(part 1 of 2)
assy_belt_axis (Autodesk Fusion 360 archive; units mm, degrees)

design "assy_belt_axis" references "circuit_mount_stepper_simple", "extrusion_ribbon_cable_sidebar", "belt_idler", "lil_foot", "belt_clip_update", "belt_motor_mount", "carriage_front_generic", "limit_mount", "FRM-Extrusion-VSlot-2020-350"
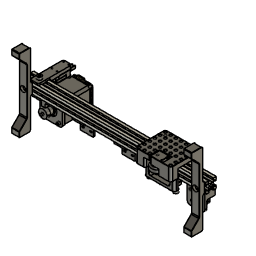
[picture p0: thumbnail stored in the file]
component_insert "Component Insert1" alignAngle 90 alignOffsetX 0 alignOffsetY 0 alignOffsetZ 0
joint "Assemble1" alignAngle -90 alignOffsetX 0 alignOffsetY 0 alignOffsetZ -6
component_insert "Component Insert2"
joint "Assemble2" alignAngle 0 alignOffsetX 0 alignOffsetY 0 alignOffsetZ -10
component_insert "Component Insert3"
joint "Assemble3" alignAngle 90 alignOffsetX 0 alignOffsetY 0 alignOffsetZ 0
component_insert "Component Insert4"
joint "Assemble4" alignAngle 0 alignOffsetX 0 alignOffsetY 30 alignOffsetZ 9
component_insert "Component Insert5"
joint "Assemble33" alignAngle 180 alignOffsetX 0 alignOffsetY -8 alignOffsetZ 11
component_insert "Component Insert6"
joint "Assemble6" alignAngle 270 alignOffsetX 0 alignOffsetY 21 alignOffsetZ 9
component_insert "Component Insert7"
joint "Assemble7" alignAngle 0 alignOffsetX 0 alignOffsetY 10 alignOffsetZ 6
component_insert "Component Insert8"
joint "Assemble8" alignAngle 0 alignOffsetX 0 alignOffsetY -10 alignOffsetZ 6
component_insert "Component Insert9"
joint "Assemble9" alignAngle 90 alignOffsetX 0 alignOffsetY 0 alignOffsetZ 0
component_insert "Component Insert32"
joint "Assemble32" alignAngle 270 alignOffsetX -70 alignOffsetY 0 alignOffsetZ 9
component_insert "Component Insert33"
joint "Assemble34" alignAngle -90 alignOffsetX 10 alignOffsetY 0 alignOffsetZ 9
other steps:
joint_origin "JointOrigin1"
joint_origin "JointOrigin2"
step "Assemble21" alignAngle -90 alignOffsetX 0 alignOffsetY 0 alignOffsetZ 0
step "Assemble22" alignAngle -90 alignOffsetX 0 alignOffsetY 0 alignOffsetZ 0
step "Assemble23" alignAngle 180 alignOffsetX 0 alignOffsetY 0 alignOffsetZ 0
step "Assemble24" alignAngle 90 alignOffsetX 0 alignOffsetY 0 alignOffsetZ 0
step "Assemble25" alignAngle 90 alignOffsetX 0 alignOffsetY 0 alignOffsetZ 0
step "Assemble26" alignAngle 90 alignOffsetX 0 alignOffsetY 0 alignOffsetZ 0
step "Assemble27" alignAngle 90 alignOffsetX 0 alignOffsetY 0 alignOffsetZ 0
step "Assemble28" alignAngle 0 alignOffsetX 0 alignOffsetY 0 alignOffsetZ 0
step "Assemble29" alignAngle 0 alignOffsetX 0 alignOffsetY 0 alignOffsetZ 0
step "Assemble30" alignAngle 0 alignOffsetX 0 alignOffsetY 0 alignOffsetZ 0
step "Assemble31" alignAngle 0 alignOffsetX 0 alignOffsetY 0 alignOffsetZ 0

design "lil_foot"
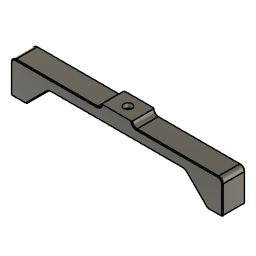
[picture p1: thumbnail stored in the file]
sketch "Sketch1" plane through (0, 0, 0) normal (0, 1, 0) x axis (1, 0, 0)
  line L1 (0, 0) -> (-10, 0)
  line L2 (-10, 3) -> (-10, 0)
  line L3 (-70, 3) -> (-10, 3)
  line L4 (-70, 25) -> (-70, 3)
  line L5 (-60, 25) -> (-70, 25)
  line L6 (-45, 10) -> (-60, 25)
  line L7 (0, 10) -> (-45, 10)
  line L8 (0, 0) -> (0, 10)
  line L9 (0, 0) -> (10, 0)
  line L10 (10, 3) -> (10, 0)
  line L11 (70, 3) -> (10, 3)
  line L12 (70, 25) -> (70, 3)
  line L13 (60, 25) -> (70, 25)
  line L14 (45, 10) -> (60, 25)
  line L15 (0, 10) -> (45, 10)
  point P1 (0, 0)
  point P9 (0, 0)
  point P10 (0, 0)
  point P2 (-10, 0)
  point P11 (10, 0)
  point P3 (-10, 3)
  point P13 (10, 3)
  point P4 (-70, 3)
  point P14 (70, 3)
  point P5 (-70, 25)
  point P15 (70, 25)
  point P6 (-60, 25)
  point P16 (60, 25)
  point P7 (-45, 10)
  point P17 (45, 10)
  point P8 (0, 10)
  point P18 (0, 10)
  point P12 (0, 0)
  horizontal L1
  perpendicular L1 L2
  perpendicular L2 L3
  perpendicular L3 L4
  perpendicular L4 L5
  perpendicular L4 L7
  perpendicular L7 L8
  coincident P1 P9
  coincident L8 P10
  coincident P1 P10
  symmetric P2 L8 P11
  symmetric P3 L8 P13
  symmetric P4 L8 P14
  symmetric P5 L8 P15
  symmetric P6 L8 P16
  symmetric P7 L8 P17
  symmetric P8 L8 P18
  symmetric L8 P10 P12
  dimension "d2" distance P2 P10 = 10
  dimension "d4" angle L6 L7 = 45
  dimension "d5" distance P5 P6 = 10
  dimension "d6" distance P6 P7 = 15
  dimension "d8" distance P5 P8 = 70 (= "( 140 / 2 ) * 1 mm")
  dimension "d9" distance P2 P3 = 3
  dimension "d11" distance P2 P5 = 25
  dimension "d12" distance P1 P8 = 10
extrude "Extrude1" new body sketch "Sketch1" profile of L1 L2 L3 L4 L5 L6 L7 L9 L10 L11 L12 L13 L14 L15 along normal blind 15
sketch "Sketch2" plane through (0, 0, 0) normal (0, 0, 1) x axis (-1, 0, 0)
  line L1 (-10, 0) -> (10, 0)
  line L2 (-10, -15) -> (-10, 0)
  line L3 (10, -15) -> (-10, -15)
  line L4 (10, 0) -> (10, -15)
  line L5 (0, -15) -> (0, 0)
  circle C1 centre (0, -7.5) radius 2.75
  circle C2 centre (0, -7.5) radius 5.25
  point P1 (0, 0)
  point P6 (0, 0)
  point P7 (0, -15)
  point P8 (0, -7.5)
  coincident P1 P6
  midpoint L3 P7
  midpoint L5 P8
  concentric C1 C2
  dimension "d15" diameter C2 = 10.5
  dimension "d16" diameter C1 = 5.5
extrude "Extrude2" cut sketch "Sketch2" profile of C1 to an object
extrude "Extrude3" cut sketch "Sketch2" profile of L2 L4 C1 C2 no distance stored from offset -5.5
chamfer "Chamfer1" distance 2.5
fillet "Fillet1" radius 3
fillet "Fillet2" radius 1
chamfer "Chamfer2" distance 0.5
named bodies: "lil_foot"

design "FRM-Extrusion-VSlot-2020-350"
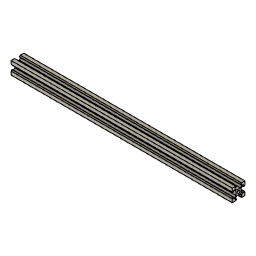
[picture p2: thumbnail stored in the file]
parameter "d90" = 4
parameter "d92" = 0.75 (= "( 1.5 / 2 ) * 1 mm")
sketch "Sketch4" plane through (0, 0, 0) normal (1, 0, 0) x axis (0, 1, 0)
  line L1 (20, 0) -> (0, 0)
  line L2 (20, 20) -> (20, 0)
  line L3 (0, 20) -> (20, 20)
  line L4 (0, 0) -> (0, 20)
  line L5 (10, 0) -> (10, 20)
  line L6 (0, 10) -> (20, 10)
  line L7 (15.5, 18.2) -> (13.125, 18.2)
  line L8 (12.9393, 14) -> (15.5, 16.5607)
  line L9 (10, 14) -> (12.9393, 14)
  line L10 (20, 20) -> (10, 10)
  line L11 (13.125, 18.545) -> (13.125, 18.2)
  line L12 (14.58, 20) -> (13.125, 18.545)
  line L13 (15.5, 16.5607) -> (15.5, 18.2)
  line L14 (20, 14.58) -> (18.545, 13.125)
  line L15 (18.545, 13.125) -> (18.2, 13.125)
  line L16 (16.5607, 15.5) -> (18.2, 15.5)
  line L17 (14, 12.9393) -> (16.5607, 15.5)
  line L18 (14, 10) -> (14, 12.9393)
  line L19 (18.2, 15.5) -> (18.2, 13.125)
  line L20 (5.42, 20) -> (6.875, 18.545)
  line L21 (6.875, 18.545) -> (6.875, 18.2)
  line L22 (4.5, 18.2) -> (6.875, 18.2)
  line L23 (4.5, 16.5607) -> (4.5, 18.2)
  line L24 (10, 14) -> (7.0607, 14)
  line L25 (7.0607, 14) -> (4.5, 16.5607)
  line L26 (0, 14.58) -> (1.455, 13.125)
  line L27 (1.455, 13.125) -> (1.8, 13.125)
  line L28 (1.8, 15.5) -> (1.8, 13.125)
  line L29 (3.4393, 15.5) -> (1.8, 15.5)
  line L30 (6, 10) -> (6, 12.9393)
  line L31 (6, 12.9393) -> (3.4393, 15.5)
  line L32 (5.42, 0) -> (6.875, 1.455)
  line L33 (6.875, 1.455) -> (6.875, 1.8)
  line L34 (4.5, 1.8) -> (6.875, 1.8)
  line L35 (4.5, 3.4393) -> (4.5, 1.8)
  line L36 (7.0607, 6) -> (4.5, 3.4393)
  line L37 (10, 6) -> (7.0607, 6)
  line L38 (14.58, 0) -> (13.125, 1.455)
  line L39 (13.125, 1.455) -> (13.125, 1.8)
  line L40 (15.5, 1.8) -> (13.125, 1.8)
  line L41 (15.5, 3.4393) -> (15.5, 1.8)
  line L42 (12.9393, 6) -> (15.5, 3.4393)
  line L43 (10, 6) -> (12.9393, 6)
  line L44 (0, 5.42) -> (1.455, 6.875)
  line L45 (1.455, 6.875) -> (1.8, 6.875)
  line L46 (1.8, 4.5) -> (1.8, 6.875)
  line L47 (3.4393, 4.5) -> (1.8, 4.5)
  line L48 (6, 10) -> (6, 7.0607)
  line L49 (6, 7.0607) -> (3.4393, 4.5)
  line L50 (20, 5.42) -> (18.545, 6.875)
  line L51 (18.545, 6.875) -> (18.2, 6.875)
  line L52 (18.2, 4.5) -> (18.2, 6.875)
  line L53 (16.5607, 4.5) -> (18.2, 4.5)
  line L54 (14, 10) -> (14, 7.0607)
  line L55 (14, 7.0607) -> (16.5607, 4.5)
  circle C1 centre (10, 10) radius 2.2
  point P1 (0, 0)
  point P2 (0, 0)
  point P6 (10, 20)
  point P7 (10, 0)
  point P8 (20, 10)
  point P9 (0, 10)
  point P12 (10, 14)
  point P13 (10, 10)
  point P14 (10, 10)
  point P16 (14.58, 20)
  point P10 (13.125, 18.2)
  point P21 (18.2, 13.125)
  point P11 (12.9393, 14)
  point P24 (14, 12.9393)
  point P25 (14, 10)
  point P15 (13.125, 18.545)
  point P19 (18.545, 13.125)
  point P20 (20, 14.58)
  point P17 (15.5, 18.2)
  point P22 (18.2, 15.5)
  point P18 (15.5, 16.5607)
  point P23 (16.5607, 15.5)
  point P28 (6.875, 18.2)
  point P31 (7.0607, 14)
  point P32 (10, 14)
  point P26 (6.875, 18.545)
  point P27 (5.42, 20)
  point P29 (4.5, 18.2)
  point P30 (4.5, 16.5607)
  point P33 (1.455, 13.125)
  point P34 (0, 14.58)
  point P35 (1.8, 13.125)
  point P36 (1.8, 15.5)
  point P37 (3.4393, 15.5)
  point P38 (6, 12.9393)
  point P39 (6, 10)
  point P49 (13.125, 1.8)
  point P52 (12.9393, 6)
  point P53 (10, 6)
  point P47 (13.125, 1.455)
  point P48 (14.58, 0)
  point P50 (15.5, 1.8)
  point P51 (15.5, 3.4393)
  point P61 (18.545, 6.875)
  point P62 (20, 5.42)
  point P63 (18.2, 6.875)
  point P64 (18.2, 4.5)
  point P65 (16.5607, 4.5)
  point P66 (14, 7.0607)
  point P67 (14, 10)
  point P40 (6.875, 1.455)
  point P41 (5.42, 0)
  point P42 (6.875, 1.8)
  point P43 (4.5, 1.8)
  point P44 (4.5, 3.4393)
  point P45 (7.0607, 6)
  point P46 (10, 6)
  point P54 (1.455, 6.875)
  point P55 (0, 5.42)
  point P56 (1.8, 6.875)
  point P57 (1.8, 4.5)
  point P58 (3.4393, 4.5)
  point P59 (6, 7.0607)
  point P60 (6, 10)
  point P3 (20, 0)
  point P4 (20, 20)
  horizontal L1
  vertical L2
  horizontal L3
  vertical L4
  coincident P1 P2
  equal L1 L4
  midpoint L3 P6
  midpoint L1 P7
  midpoint L2 P8
  midpoint L4 P9
  coincident L5 P12
  perpendicular L5 L9
  midpoint L5 P13
  coincident P13 P14
  parallel L8 L10
  perpendicular L7 L11
  coincident L3 P16
  parallel L10 L12
  perpendicular L7 L13
  horizontal L7
  symmetric P10 L10 P21
  symmetric P11 L10 P24
  symmetric P12 L10 P25
  symmetric L10 P15 P19
  symmetric L10 P16 P20
  symmetric L10 P17 P22
  symmetric L10 P18 P23
  symmetric L5 P10 P28
  symmetric L5 P11 P31
  symmetric L5 P12 P32
  symmetric L5 P15 P26
  symmetric L5 P16 P27
  symmetric L5 P17 P29
  symmetric L5 P18 P30
  symmetric L5 P19 P33
  symmetric L5 P20 P34
  symmetric L5 P21 P35
  symmetric L5 P22 P36
  symmetric L5 P23 P37
  symmetric L5 P24 P38
  symmetric L5 P25 P39
  symmetric L6 P10 P49
  symmetric L6 P11 P52
  symmetric L6 P12 P53
  symmetric L6 P15 P47
  symmetric L6 P16 P48
  symmetric L6 P17 P50
  symmetric L6 P18 P51
  symmetric L6 P19 P61
  symmetric L6 P20 P62
  symmetric L6 P21 P63
  symmetric L6 P22 P64
  symmetric L6 P23 P65
  symmetric L6 P24 P66
  symmetric L6 P25 P67
  symmetric L6 P26 P40
  symmetric L6 P27 P41
  symmetric L6 P28 P42
  symmetric L6 P29 P43
  symmetric L6 P30 P44
  symmetric L6 P31 P45
  symmetric L6 P32 P46
  symmetric L6 P33 P54
  symmetric L6 P34 P55
  symmetric L6 P35 P56
  symmetric L6 P36 P57
  symmetric L6 P37 P58
  symmetric L6 P38 P59
  symmetric L6 P39 P60
  dimension "d177" distance P2 P3 = 20
  dimension "d178" diameter C1 = 4.4
  dimension "d181" distance P4 L8 = 0.75 (= "( 1.5 / 2 ) * 1 mm")
  dimension "d182" distance L9 P13 = 4
  dimension "d215" distance P6 L13 = 5.5 (= "( 11 / 2 ) * 1 mm")
  dimension "d216" distance P6 P10 = 3.125 (= "( 6.25 / 2 ) * 1 mm")
  dimension "d217" distance P6 P16 = 4.58 (= "( 9.16 / 2 ) * 1 mm")
  dimension "d219" distance P4 P17 = 1.8
  dimension "d220" distance P10 L9 = 4.2
  dimension "d32" distance = 3 (= "( 6 / 2 ) * 1 mm")
  dimension "d33" distance = 3 (= "d32")
  dimension "d34" distance = 3 (= "d33")
  dimension "d35" distance = 3 (= "d32")
  dimension "d43" distance = 2
  dimension "d44" distance = 2 (= "d43")
extrude "Extrude3" new body sketch "Sketch4" profile of L1 L2 L3 L4 L7 L8 L9 C1 L11 L12 L13 L14 L15 L16 L17 L18 L19 L20 L21 L22 L23 L24 L25 L26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 along normal blind 350
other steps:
step "Extrude" AlongDistance -1.5 TaperAngle 0
step "Fillet" ChordLen 3
step "Chamfer5" Distance 0.5
step "Chamfer6" Distance 1

design "HW_M5x25-SHCS"
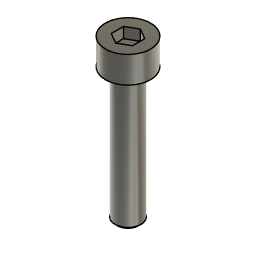
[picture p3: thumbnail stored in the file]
sketch "Sketch1" plane through (0, 0, 0) normal (0, 1, 0) x axis (1, 0, 0)
  line L1 (0, 25) -> (0, -5)
  line L2 (1.95, 25) -> (0, 25)
  line L3 (2.45, 24.5) -> (1.95, 25)
  line L4 (2.45, 0) -> (2.45, 24.5)
  line L5 (4.25, 0) -> (2.45, 0)
  line L6 (4.25, -5) -> (4.25, 0)
  line L7 (0, -5) -> (4.25, -5)
  point P1 (0, 0)
  point P4 (1.95, 25)
  point P5 (2.45, 24.5)
  point P3 (0, 25)
  point P7 (4.25, 0)
  point P8 (4.25, -5)
  point P2 (0, -5)
  vertical L1
  perpendicular L1 L2
  perpendicular L2 L4
  perpendicular L4 L5
  perpendicular L5 L6
  horizontal L7
  coincident P1 L1
  coincident P1 L5
  dimension "d1" distance P1 L2 = 25
  dimension "d2" angle L2 L3 = 45
  dimension "d3" distance P4 P5 = 0.5
  dimension "d4" distance P3 L4 = 2.45 (= "( 4.9 / 2 ) * 1 mm")
  dimension "d5" distance P7 P8 = 5
  dimension "d6" distance P2 P8 = 4.25 (= "( 8.5 / 2 ) * 1 mm")
revolve "Revolve1" sketch "Sketch1" AlongAngle 360
sketch "Sketch2" plane through (0, 0, 5) normal (0, 0, 1) x axis (-1, 0, 0)
  line L1 (0, -2.3094) -> (-2, -1.1547)
  line L2 (2, -1.1547) -> (0, -2.3094)
  line L3 (2, 1.1547) -> (2, -1.1547)
  line L4 (0, 2.3094) -> (2, 1.1547)
  line L5 (-2, 1.1547) -> (0, 2.3094)
  line L6 (-2, -1.1547) -> (-2, 1.1547)
  circle C1 centre (0, 0) radius 4.25
  point P1 (0, 0)
  point P9 (0, 0)
  point P5 (2, -1.1547)
  coincident P1 P9
  vertical L6
  dimension "d8" distance P5 L6 = 4
extrude "Extrude1" cut sketch "Sketch2" profile of L1 L2 L3 L4 L5 L6 against normal blind 2

design "PP_ACTU_N17-Stepper"
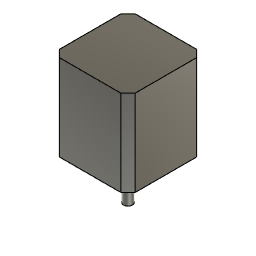
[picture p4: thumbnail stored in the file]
description: Nema 17 Stepper, 48mm Length Preferred, 5mm Shaft
sketch "Sketch1" plane through (0, 0, 0) normal (0, 0, 1) x axis (1, 0, 0)
  line L1 (-21.15, 21.15) -> (21.15, 21.15)
  line L2 (-21.15, -21.15) -> (-21.15, 21.15)
  line L3 (21.15, -21.15) -> (-21.15, -21.15)
  line L4 (21.15, 21.15) -> (21.15, -21.15)
  line L5 (-21.15, -21.15) -> (21.15, 21.15)
  line L6 (21.15, -21.15) -> (-21.15, 21.15)
  line L7 (15.5, 15.5) -> (-15.5, 15.5)
  line L8 (15.5, -15.5) -> (15.5, 15.5)
  line L9 (-15.5, -15.5) -> (15.5, -15.5)
  line L10 (-15.5, 15.5) -> (-15.5, -15.5)
  circle C1 centre (0, 0) radius 11
  circle C2 centre (-15.5, 15.5) radius 1.5
  circle C3 centre (-15.5, -15.5) radius 1.5
  circle C4 centre (15.5, -15.5) radius 1.5
  circle C5 centre (15.5, 15.5) radius 1.5
  circle C6 centre (0, 0) radius 2.5
  point P6 (0, 0)
  point P1 (0, 0)
  point P7 (0, 0)
  point P10 (15.5, -15.5)
  point P8 (-15.5, 15.5)
  point P9 (15.5, 15.5)
  point P12 (-15.5, 15.5)
  point P11 (-15.5, -15.5)
  point P13 (-15.5, -15.5)
  point P14 (15.5, -15.5)
  point P15 (15.5, 15.5)
  point P2 (21.15, 21.15)
  point P3 (-21.15, 21.15)
  perpendicular L1 L2
  parallel L1 L3
  parallel L2 L4
  horizontal L1
  coincident L5 P6
  coincident L6 P6
  coincident P1 P6
  equal L1 L2
  coincident P6 P7
  horizontal L7
  vertical L8
  horizontal L9
  vertical L10
  coincident L6 P10
  coincident L6 P8
  coincident L5 P9
  coincident P8 P12
  coincident P11 P13
  coincident P10 P14
  coincident P9 P15
  equal C2 C5
  equal C2 C3
  equal C2 C4
  concentric C1 C6
  dimension "d1" distance P2 P3 = 42.3
  dimension "d2" diameter C1 = 22
  dimension "d3" distance P8 P9 = 31
  dimension "d4" diameter C2 = 3
  dimension "d5" diameter C6 = 5
  dimension "d19" alignAngle = 0
  dimension "d20" alignOffsetX = 0
  dimension "d21" alignOffsetY = 0
  dimension "d22" alignOffsetZ = 0
  dimension "d23" alignAngle = 180
  dimension "d24" alignOffsetX = 0
  dimension "d25" alignOffsetY = 0
  dimension "d26" alignOffsetZ = 0
extrude "Extrude1" new body sketch "Sketch1" profile of L1 L2 L3 L4 C1 C2 C3 C4 C5 C6 along normal blind 48
extrude "Extrude2" cut sketch "Sketch1" profile of C2 C3 C4 C5 along normal blind 5
extrude "Extrude3" add sketch "Sketch1" profile of C1 C6 against normal blind 2
extrude "Extrude4" add sketch "Sketch1" profile of C6 against normal blind 24
chamfer "Chamfer1" distance 4

design "PP_TRNS_V-Wheel"
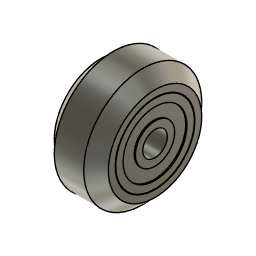
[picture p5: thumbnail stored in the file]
sketch "Sketch1" plane through (0, 0, 0) normal (0, 1, 0) x axis (1, 0, 0)
  line L1 (0, -2.5) -> (0, -12)
  line L2 (3, -12) -> (0, -12)
  line L3 (5.5, -9.5) -> (3, -12)
  line L4 (5.5, -8.1) -> (5.5, -9.5)
  line L5 (5.25, -8.1) -> (5.5, -8.1)
  line L6 (5.25, -8) -> (5.25, -8.1)
  line L7 (5.5, -8) -> (5.25, -8)
  line L8 (5.5, -6.5) -> (5.5, -8)
  line L9 (5.25, -6.5) -> (5.5, -6.5)
  line L10 (5.25, -4) -> (5.25, -6.5)
  line L11 (5.5, -4) -> (5.25, -4)
  line L12 (5.5, -2.5) -> (5.5, -4)
  line L13 (0, -2.5) -> (5.5, -2.5)
  point P1 (0, 0)
  point P12 (5.5, -4)
  point P10 (5.25, -6.5)
  point P8 (5.5, -8)
  point P2 (0, -12)
  point P13 (5.5, -2.5)
  point P14 (0, -2.5)
  point P9 (5.5, -6.5)
  point P11 (5.25, -4)
  point P3 (3, -12)
  point P6 (5.25, -8.1)
  point P7 (5.25, -8)
  vertical L1
  perpendicular L1 L2
  perpendicular L2 L4
  perpendicular L4 L5
  perpendicular L5 L6
  perpendicular L6 L7
  perpendicular L5 L8
  perpendicular L8 L9
  perpendicular L9 L10
  perpendicular L10 L11
  perpendicular L9 L12
  perpendicular L12 L13
  coincident P1 L1
  coincident L8 P12
  coincident L6 P10
  coincident L4 P8
  dimension "d1" distance P1 L13 = 2.5
  dimension "d2" distance P1 P2 = 12 (= "( 24 / 2 ) * 1 mm")
  dimension "d3" distance P13 P14 = 5.5 (= "( 11 / 2 ) * 1 mm")
  dimension "d4" distance P12 P13 = 1.5
  dimension "d5" distance P8 P9 = 1.5
  dimension "d6" distance P11 P12 = 0.25
  dimension "d7" distance P2 P3 = 3 (= "( 6 / 2 ) * 1 mm")
  dimension "d8" distance P6 P7 = 0.1
  dimension "d9" distance P1 P8 = 8
  dimension "d10" angle L2 L3 = 45
revolve "Revolve1" sketch "Sketch1" AlongAngle 360
mirror "Mirror1" mirrorStitchTolerance 0.1

design "extrusion_ribbon_cable_sidebar" references "HW_M3x8-SHCS", "HW_M5x8-SHCS"
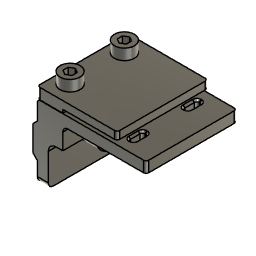
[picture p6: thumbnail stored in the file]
sketch "Sketch4" plane through (0, 0, 0) normal (0, 1, 0) x axis (1, 0, 0)
  line L1 (0, 20) -> (0, 0)
  line L2 (3, 20) -> (0, 20)
  line L3 (3, 3) -> (3, 20)
  line L4 (30, 3) -> (3, 3)
  line L5 (30, 0) -> (30, 3)
  line L6 (0, 0) -> (30, 0)
  line L7 (-2, 12.75) -> (0, 14.75)
  line L8 (-2, 7.25) -> (-2, 12.75)
  line L9 (0, 5.25) -> (-2, 7.25)
  line L10 (0, 10) -> (-2, 10)
  line L11 (-1.25, 13.5) -> (-1.25, 6.5)
  line L12 (7, -1) -> (22, -1)
  line L13 (7, -0.1) -> (7, -1)
  line L14 (0, -0.1) -> (7, -0.1)
  line L15 (0, -3.1) -> (0, -0.1)
  line L16 (22, -3.1) -> (0, -3.1)
  line L17 (22, -1) -> (22, -3.1)
  line L18 (7, 8.9) -> (7, 3)
  line L19 (3, 8.9) -> (7, 8.9)
  point P1 (0, 0)
  point P2 (0, 0)
  point P8 (0, 0)
  point P9 (0, 14.75)
  point P12 (0, 5.25)
  point P13 (-2, 10)
  point P14 (0, 10)
  point P15 (-1.25, 6.5)
  point P16 (-1.25, 13.5)
  point P17 (22, -1)
  point P23 (22, -1)
  point P24 (7, 3)
  point P26 (3, 8.9)
  point P19 (7, -0.1)
  point P3 (0, 20)
  point P10 (-2, 12.75)
  point P11 (-2, 7.25)
  point P4 (3, 20)
  point P6 (30, 3)
  point P7 (30, 0)
  point P20 (0, -0.1)
  point P21 (0, -3.1)
  point P18 (7, -1)
  coincident P1 P2
  vertical L1
  perpendicular L1 L2
  perpendicular L2 L3
  perpendicular L1 L4
  perpendicular L4 L5
  perpendicular L5 L6
  coincident P1 P8
  coincident L1 P9
  perpendicular L2 L8
  coincident L1 P12
  perpendicular L7 L9
  midpoint L8 P13
  midpoint L1 P14
  horizontal L10
  coincident L9 P15
  coincident L7 P16
  vertical L11
  horizontal L12
  perpendicular L6 L13
  perpendicular L13 L14
  perpendicular L14 L15
  perpendicular L15 L16
  perpendicular L16 L17
  coincident P17 P23
  coincident P1 L15
  coincident L4 P24
  perpendicular L4 L18
  coincident L3 P26
  perpendicular L3 L19
  coincident P19 L18
  dimension "d38" distance P2 P3 = 20
  dimension "d39" distance P10 P11 = 5.5
  dimension "d40" distance L1 L8 = 2
  dimension "d42" angle L8 L9 = 45
  dimension "d44" distance P3 P4 = 3
  dimension "d45" distance P6 P7 = 3
  dimension "d46" distance P7 P8 = 30
  dimension "d47" distance L6 L14 = 0.1
  dimension "d48" distance L6 L12 = 1
  dimension "d49" distance P20 P21 = 3
  dimension "d50" distance P17 P18 = 15
  dimension "d51" distance P19 P20 = 7
  dimension "d52" distance L16 L19 = 12
  dimension "d112" distance L1 L11 = 1.25
extrude "Extrude4" new body sketch "Sketch4" profile of L1 L2 L3 L4 L5 L6 L7 L9 L11 L12 L13 L14 L15 L16 L17 along normal blind 25 bodies "sidebar_cap"
sketch "Sketch5" plane through (0, 0, 3.1) normal (0, 0, 1) x axis (-1, 0, 0)
  line L1 (-22, 0) -> (0, 0)
  line L2 (-22, -25) -> (-22, 0)
  line L3 (0, -25) -> (-22, -25)
  line L4 (0, 0) -> (0, -25)
  line L5 (-7, -25) -> (-7, 0)
  line L6 (-4, -25) -> (-4, 0)
  line L7 (-22, -12.5) -> (-4, -12.5)
  circle C1 centre (-4, -5) radius 1.35
  circle C2 centre (-4, -5) radius 3
  circle C3 centre (-4, -5) radius 1.65
  circle C4 centre (-4, -20) radius 1.65
  circle C5 centre (-4, -20) radius 1.35
  circle C6 centre (-4, -20) radius 3
  point P6 (-7, 0)
  point P7 (-7, -25)
  point P8 (-7, 0)
  point P11 (-4, 0)
  point P12 (-4, -25)
  point P14 (-4, -5)
  point P15 (-4, -12.5)
  point P16 (-22, -12.5)
  point P13 (0, 0)
  coincident L1 P6
  coincident L3 P7
  perpendicular L3 L5
  coincident P6 P8
  concentric C1 C2
  coincident L1 P11
  coincident L3 P12
  perpendicular L3 L6
  concentric C2 C3
  coincident L6 P14
  midpoint L6 P15
  midpoint L2 P16
  symmetric C1 L7 C5
  symmetric C2 L7 C6
  symmetric C3 L7 C4
  dimension "d55" diameter C2 = 6
  dimension "d56" distance P11 P13 = 4
  dimension "d57" diameter C1 = 2.7
  dimension "d58" diameter C3 = 3.3
  dimension "d59" distance P11 P14 = 5
extrude "Extrude5" sketch "Sketch4" profile of L3 L4 L18 L19 blind 8
extrude "Extrude6" sketch "Sketch4" profile of L3 L4 L18 L19 blind 8
extrude "Extrude7" cut sketch "Sketch5" profile of C1 C5 to an object offset 1
extrude "Extrude8" cut sketch "Sketch5" profile of C1 C3 C4 C5 to an object
sketch "Sketch6" plane through (3, 0, 0) normal (1, 0, 0) x axis (0, 1, 0)
  line L1 (24, -8.9) -> (24, -3)
  line L2 (16, -8.9) -> (24, -8.9)
  line L3 (16, -3) -> (16, -8.9)
  line L4 (9, -3) -> (16, -3)
  line L5 (9, -8.9) -> (9, -3)
  line L6 (1, -8.9) -> (9, -8.9)
  line L7 (1, -3) -> (1, -8.9)
  line L8 (0, -3) -> (1, -3)
  line L9 (0, -20) -> (0, -3)
  line L10 (25, -20) -> (0, -20)
  line L11 (25, -3) -> (25, -20)
  line L12 (24, -3) -> (25, -3)
  line L13 (25, -10) -> (0, -10)
  circle C1 centre (12.5, -10) radius 2.75
  circle C2 centre (12.5, -10) radius 4.25
  circle C3 centre (12.5, -10) radius 4.5
  point P14 (0, -10)
  point P15 (0, -10)
  point P16 (25, -10)
  point P17 (12.5, -10)
  coincident P14 P15
  coincident L11 P16
  perpendicular L11 L13
  midpoint L13 P17
  concentric C1 C2
  concentric C1 C3
  dimension "d70" diameter C2 = 8.5
  dimension "d71" diameter C1 = 5.5
  dimension "d77" diameter C3 = 9
extrude "Extrude9" cut sketch "Sketch6" profile of C1 no distance stored
component_insert "Component Insert3"
joint "Assemble3" alignAngle 0 alignOffsetX 0 alignOffsetY 0 alignOffsetZ 0
extrude "Extrude10" cut sketch "Sketch6" profile of L2 L3 L5 L6 C1 C3 along normal blind 7.5
extrude "Extrude11" add of existing geometry to an object
extrude "Extrude12" add of existing geometry to an object
fillet "Fillet4" ChordLen 3
fillet "Fillet5" ChordLen 1
fillet "Fillet6" ChordLen 2
fillet "Fillet7" ChordLen 2
fillet "Fillet8" ChordLen 1
sketch "Sketch7" plane through (0, 0, 0) normal (0, 0, 1) x axis (-1, 0, 0)
  line L1 (-30, 0) -> (0, 0)
  line L2 (-30, -25) -> (-30, 0)
  line L3 (0, -25) -> (-30, -25)
  line L4 (0, 0) -> (0, -25)
  line L5 (-22, -3) -> (-23.5, -3)
  line L6 (-22, -7) -> (-22, -3)
  line L7 (-23.5, -7) -> (-22, -7)
  line L8 (-23.5, -3) -> (-23.5, -7)
  line L9 (0, -12.5) -> (-30, -12.5)
  line L10 (-22, -18) -> (-22, -22)
  line L11 (-23.5, -18) -> (-22, -18)
  line L12 (-22, -22) -> (-23.5, -22)
  line L13 (-23.5, -22) -> (-23.5, -18)
  circle C1 centre (-4, -5) radius 1.35
  circle C2 centre (-4, -20) radius 1.35
  point P12 (-30, -12.5)
  point P13 (0, -12.5)
  point P14 (-22, 0)
  point P8 (-23.5, -3)
  point P18 (-23.5, -22)
  point P9 (-22, -3)
  point P15 (-22, -22)
  point P10 (-22, -7)
  point P16 (-22, -18)
  point P11 (-23.5, -7)
  point P17 (-23.5, -18)
  horizontal L5
  vertical L6
  horizontal L7
  vertical L8
  midpoint L2 P12
  midpoint L4 P13
  coincident L6 P14
  symmetric P8 L9 P18
  symmetric P9 L9 P15
  symmetric P10 L9 P16
  symmetric P11 L9 P17
  dimension "d94" distance L1 L5 = 3
  dimension "d95" distance P8 P9 = 1.5
  dimension "d96" distance P8 P11 = 4
extrude "Extrude13" cut sketch "Sketch7" profile of L5 L6 L7 L8 L10 L11 L12 L13 to an object
fillet "Fillet9" ChordLen 1
fillet "Fillet10" ChordLen 1
chamfer "Chamfer3" distance 0.5
chamfer "Chamfer4" distance 1.35
chamfer "Chamfer5" distance 0.5
component_insert "Component Insert4"
component_insert "Component Insert5"
joint "Assemble4" alignAngle 0 alignOffsetX 0 alignOffsetY 0 alignOffsetZ 0
joint "Assemble5" alignAngle 0 alignOffsetX 0 alignOffsetY 0 alignOffsetZ 0
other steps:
joint_origin "JointOrigin2"
joint_origin "JointOrigin3"
joint_origin "JointOrigin4"
named bodies: "sidebar_main", "sidebar_cap"

design "HW_M3x8-SHCS"
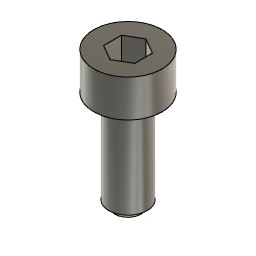
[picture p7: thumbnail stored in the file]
sketch "Sketch1" plane through (0, 0, 0) normal (0, 1, 0) x axis (1, 0, 0)
  line L1 (0, 8) -> (0, -3)
  line L2 (1.05, 8) -> (0, 8)
  line L3 (1.55, 7.5) -> (1.05, 8)
  line L4 (1.55, 0) -> (1.55, 7.5)
  line L5 (2.75, 0) -> (1.55, 0)
  line L6 (2.75, -3) -> (2.75, 0)
  line L7 (0, -3) -> (2.75, -3)
  point P1 (0, 0)
  point P4 (1.05, 8)
  point P5 (1.55, 7.5)
  point P3 (0, 8)
  point P7 (2.75, 0)
  point P8 (2.75, -3)
  point P2 (0, -3)
  vertical L1
  perpendicular L1 L2
  perpendicular L2 L4
  perpendicular L4 L5
  perpendicular L5 L6
  horizontal L7
  coincident P1 L1
  coincident P1 L5
  dimension "d1" distance P1 L2 = 8
  dimension "d2" angle L2 L3 = 45
  dimension "d3" distance P4 P5 = 0.5
  dimension "d4" distance P3 L4 = 1.55 (= "( 3.1 / 2 ) * 1 mm")
  dimension "d5" distance P7 P8 = 3
  dimension "d6" distance P2 P8 = 2.75 (= "( 5.5 / 2 ) * 1 mm")
revolve "Revolve1" sketch "Sketch1" AlongAngle 360
sketch "Sketch2" plane through (0, 0, 3) normal (0, 0, 1) x axis (-1, 0, 0)
  line L1 (0, -1.4434) -> (-1.25, -0.7217)
  line L2 (1.25, -0.7217) -> (0, -1.4434)
  line L3 (1.25, 0.7217) -> (1.25, -0.7217)
  line L4 (0, 1.4434) -> (1.25, 0.7217)
  line L5 (-1.25, 0.7217) -> (0, 1.4434)
  line L6 (-1.25, -0.7217) -> (-1.25, 0.7217)
  circle C1 centre (0, 0) radius 2.75
  point P1 (0, 0)
  point P9 (0, 0)
  point P5 (1.25, -0.7217)
  coincident P1 P9
  vertical L6
  dimension "d8" distance P5 L6 = 2.5
extrude "Extrude1" cut sketch "Sketch2" profile of L1 L2 L3 L4 L5 L6 against normal blind 2

design "HW_M5x20-SHCS"
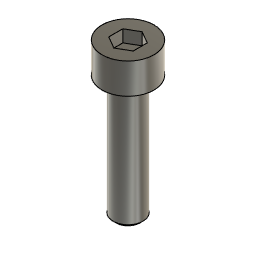
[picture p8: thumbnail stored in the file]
sketch "Sketch1" plane through (0, 0, 0) normal (0, 1, 0) x axis (1, 0, 0)
  line L1 (0, 20) -> (0, -5)
  line L2 (1.95, 20) -> (0, 20)
  line L3 (2.45, 19.5) -> (1.95, 20)
  line L4 (2.45, 0) -> (2.45, 19.5)
  line L5 (4.25, 0) -> (2.45, 0)
  line L6 (4.25, -5) -> (4.25, 0)
  line L7 (0, -5) -> (4.25, -5)
  point P1 (0, 0)
  point P4 (1.95, 20)
  point P5 (2.45, 19.5)
  point P3 (0, 20)
  point P7 (4.25, 0)
  point P8 (4.25, -5)
  point P2 (0, -5)
  vertical L1
  perpendicular L1 L2
  perpendicular L2 L4
  perpendicular L4 L5
  perpendicular L5 L6
  horizontal L7
  coincident P1 L1
  coincident P1 L5
  dimension "d1" distance P1 L2 = 20
  dimension "d2" angle L2 L3 = 45
  dimension "d3" distance P4 P5 = 0.5
  dimension "d4" distance P3 L4 = 2.45 (= "( 4.9 / 2 ) * 1 mm")
  dimension "d5" distance P7 P8 = 5
  dimension "d6" distance P2 P8 = 4.25 (= "( 8.5 / 2 ) * 1 mm")
revolve "Revolve1" sketch "Sketch1" AlongAngle 360
sketch "Sketch2" plane through (0, 0, 5) normal (0, 0, 1) x axis (-1, 0, 0)
  line L1 (0, -2.3094) -> (-2, -1.1547)
  line L2 (2, -1.1547) -> (0, -2.3094)
  line L3 (2, 1.1547) -> (2, -1.1547)
  line L4 (0, 2.3094) -> (2, 1.1547)
  line L5 (-2, 1.1547) -> (0, 2.3094)
  line L6 (-2, -1.1547) -> (-2, 1.1547)
  circle C1 centre (0, 0) radius 4.25
  point P1 (0, 0)
  point P9 (0, 0)
  point P5 (2, -1.1547)
  coincident P1 P9
  vertical L6
  dimension "d8" distance P5 L6 = 4
extrude "Extrude1" cut sketch "Sketch2" profile of L1 L2 L3 L4 L5 L6 against normal blind 2

design "PP_BRNG_625F-5x16x5"
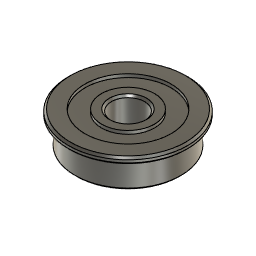
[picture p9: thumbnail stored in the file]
sketch "Sketch1" plane through (0, 0, 0) normal (0, 1, 0) x axis (1, 0, 0)
  line L1 (4, -2.5) -> (2.5, -2.5)
  line L2 (2.5, 2.5) -> (4, 2.5)
  line L3 (2.5, -2.5) -> (2.5, 2.5)
  line L4 (8, -2.5) -> (6.5, -2.5)
  line L5 (8, 2.5) -> (8, -2.5)
  line L6 (6.5, 2.5) -> (8, 2.5)
  line L7 (6.5, -2) -> (4, -2)
  line L8 (6.5, 2) -> (4, 2)
  line L9 (4, -2) -> (4, -2.5)
  line L10 (4, 2.5) -> (4, 2)
  line L11 (6.5, 2) -> (6.5, 2.5)
  line L12 (6.5, -2.5) -> (6.5, -2)
  line L13 (0, 0) -> (8, 0)
  line L14 (9, -2.5) -> (8, -2.5)
  line L15 (9, -1.5) -> (9, -2.5)
  line L16 (8, -1.5) -> (9, -1.5)
  point P11 (6.5, -2)
  point P12 (4, 2)
  point P14 (8, 0)
  point P1 (0, 0)
  point P15 (0, 0)
  point P16 (2.5, 0)
  point P6 (6.5, -2.5)
  point P19 (8, -1.5)
  point P3 (4, -2.5)
  point P10 (4, -2)
  point P7 (8, -2.5)
  point P8 (8, 2.5)
  point P2 (2.5, -2.5)
  point P17 (9, -2.5)
  point P18 (9, -1.5)
  horizontal L1
  vertical L9
  horizontal L2
  vertical L3
  horizontal L4
  vertical L5
  horizontal L6
  vertical L11
  coincident P11 L11
  perpendicular L7 L11
  coincident P12 L9
  perpendicular L8 L9
  collinear L9 L10
  collinear L11 L12
  midpoint L5 P14
  coincident P1 P15
  horizontal L13
  midpoint L3 P16
  coincident L13 P16
  equal L1 L4
  equal L9 L10
  coincident L1 P6
  perpendicular L5 L14
  perpendicular L4 L15
  coincident L5 P19
  perpendicular L5 L16
  dimension "d1" distance P1 L3 = 2.5 (= "( 5 / 2 ) * 1 mm")
  dimension "d2" distance P1 L5 = 8 (= "( 16 / 2 ) * 1 mm")
  dimension "d4" distance P3 P10 = 0.5
  dimension "d5" distance P7 P8 = 5
  dimension "d8" distance P2 P3 = 1.5
  dimension "d9" distance P17 P18 = 1
  dimension "d10" distance P1 P17 = 9 (= "( 18 / 2 ) * 1 mm")
revolve "Revolve1" sketch "Sketch1" AlongAngle 360
chamfer "Chamfer1" distance 0.3

design "HW_M5x10-SHCS"
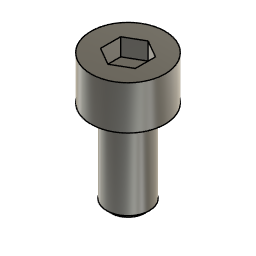
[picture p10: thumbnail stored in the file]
sketch "Sketch1" plane through (0, 0, 0) normal (0, 1, 0) x axis (1, 0, 0)
  line L1 (0, 10) -> (0, -5)
  line L2 (1.95, 10) -> (0, 10)
  line L3 (2.45, 9.5) -> (1.95, 10)
  line L4 (2.45, 0) -> (2.45, 9.5)
  line L5 (4.25, 0) -> (2.45, 0)
  line L6 (4.25, -5) -> (4.25, 0)
  line L7 (0, -5) -> (4.25, -5)
  point P1 (0, 0)
  point P4 (1.95, 10)
  point P5 (2.45, 9.5)
  point P3 (0, 10)
  point P7 (4.25, 0)
  point P8 (4.25, -5)
  point P2 (0, -5)
  vertical L1
  perpendicular L1 L2
  perpendicular L2 L4
  perpendicular L4 L5
  perpendicular L5 L6
  horizontal L7
  coincident P1 L1
  coincident P1 L5
  dimension "d1" distance P1 L2 = 10
  dimension "d2" angle L2 L3 = 45
  dimension "d3" distance P4 P5 = 0.5
  dimension "d4" distance P3 L4 = 2.45 (= "( 4.9 / 2 ) * 1 mm")
  dimension "d5" distance P7 P8 = 5
  dimension "d6" distance P2 P8 = 4.25 (= "( 8.5 / 2 ) * 1 mm")
revolve "Revolve1" sketch "Sketch1" AlongAngle 360
sketch "Sketch2" plane through (0, 0, 5) normal (0, 0, 1) x axis (-1, 0, 0)
  line L1 (0, -2.3094) -> (-2, -1.1547)
  line L2 (2, -1.1547) -> (0, -2.3094)
  line L3 (2, 1.1547) -> (2, -1.1547)
  line L4 (0, 2.3094) -> (2, 1.1547)
  line L5 (-2, 1.1547) -> (0, 2.3094)
  line L6 (-2, -1.1547) -> (-2, 1.1547)
  circle C1 centre (0, 0) radius 4.25
  point P1 (0, 0)
  point P9 (0, 0)
  point P5 (2, -1.1547)
  coincident P1 P9
  vertical L6
  dimension "d8" distance P5 L6 = 4
extrude "Extrude1" cut sketch "Sketch2" profile of L1 L2 L3 L4 L5 L6 against normal blind 2

design "HW_M5x8-SHCS"
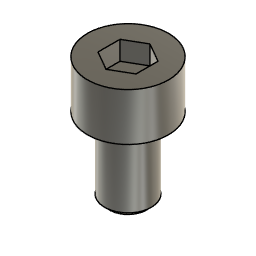
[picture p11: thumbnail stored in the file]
sketch "Sketch1" plane through (0, 0, 0) normal (0, 1, 0) x axis (1, 0, 0)
  line L1 (0, 8) -> (0, -5)
  line L2 (1.95, 8) -> (0, 8)
  line L3 (2.45, 7.5) -> (1.95, 8)
  line L4 (2.45, 0) -> (2.45, 7.5)
  line L5 (4.25, 0) -> (2.45, 0)
  line L6 (4.25, -5) -> (4.25, 0)
  line L7 (0, -5) -> (4.25, -5)
  point P1 (0, 0)
  point P4 (1.95, 8)
  point P5 (2.45, 7.5)
  point P3 (0, 8)
  point P7 (4.25, 0)
  point P8 (4.25, -5)
  point P2 (0, -5)
  vertical L1
  perpendicular L1 L2
  perpendicular L2 L4
  perpendicular L4 L5
  perpendicular L5 L6
  horizontal L7
  coincident P1 L1
  coincident P1 L5
  dimension "d1" distance P1 L2 = 8
  dimension "d2" angle L2 L3 = 45
  dimension "d3" distance P4 P5 = 0.5
  dimension "d4" distance P3 L4 = 2.45 (= "( 4.9 / 2 ) * 1 mm")
  dimension "d5" distance P7 P8 = 5
  dimension "d6" distance P2 P8 = 4.25 (= "( 8.5 / 2 ) * 1 mm")
revolve "Revolve1" sketch "Sketch1" AlongAngle 360
sketch "Sketch2" plane through (0, 0, 5) normal (0, 0, 1) x axis (-1, 0, 0)
  line L1 (0, -2.3094) -> (-2, -1.1547)
  line L2 (2, -1.1547) -> (0, -2.3094)
  line L3 (2, 1.1547) -> (2, -1.1547)
  line L4 (0, 2.3094) -> (2, 1.1547)
  line L5 (-2, 1.1547) -> (0, 2.3094)
  line L6 (-2, -1.1547) -> (-2, 1.1547)
  circle C1 centre (0, 0) radius 4.25
  point P1 (0, 0)
  point P9 (0, 0)
  point P5 (2, -1.1547)
  coincident P1 P9
  vertical L6
  dimension "d8" distance P5 L6 = 4
extrude "Extrude1" cut sketch "Sketch2" profile of L1 L2 L3 L4 L5 L6 against normal blind 2

design "circuit_mount_stepper_simple" references "circuit_modular_stepper"
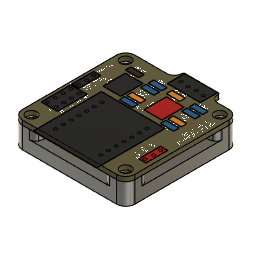
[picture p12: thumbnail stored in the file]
sketch "Sketch1" plane through (0, 0, 0) normal (0, 0, 1) x axis (1, 0, 0)
  line L1 (-18.5, 18.5) -> (18.5, 18.5)
  line L2 (-18.5, -18.5) -> (-18.5, 18.5)
  line L3 (18.5, -18.5) -> (-18.5, -18.5)
  line L4 (18.5, 18.5) -> (18.5, -18.5)
  line L5 (-18.5, -18.5) -> (18.5, 18.5)
  line L6 (18.5, -18.5) -> (-18.5, 18.5)
  line L7 (15.5, 15.5) -> (-15.5, 15.5)
  line L8 (15.5, -15.5) -> (15.5, 15.5)
  line L9 (-15.5, -15.5) -> (15.5, -15.5)
  line L10 (-15.5, 15.5) -> (-15.5, -15.5)
  circle C1 centre (15.5, 15.5) radius 1.7
  circle C2 centre (-15.5, 15.5) radius 1.7
  circle C3 centre (-15.5, -15.5) radius 1.7
  circle C4 centre (15.5, -15.5) radius 1.7
  circle C5 centre (-15.5, 15.5) radius 4.5
  circle C6 centre (15.5, 15.5) radius 4.5
  circle C7 centre (15.5, -15.5) radius 4.5
  circle C8 centre (-15.5, -15.5) radius 4.5
  circle C9 centre (0, 0) radius 15
  circle C10 centre (0, 0) radius 2.5
  circle C11 centre (0, 0) radius 4
  circle C12 centre (0, 0) radius 6.5
  point P6 (0, 0)
  point P1 (0, 0)
  point P9 (15.5, -15.5)
  point P7 (-15.5, 15.5)
  point P8 (15.5, 15.5)
  point P11 (15.5, 15.5)
  point P12 (-15.5, 15.5)
  point P10 (-15.5, -15.5)
  point P13 (-15.5, -15.5)
  point P14 (15.5, -15.5)
  point P19 (0, 0)
  point P21 (0, 0)
  point P2 (18.5, 18.5)
  point P3 (-18.5, 18.5)
  horizontal L1
  perpendicular L1 L2
  parallel L1 L3
  parallel L2 L4
  coincident L5 P6
  coincident L6 P6
  coincident P1 P6
  equal L1 L4
  horizontal L7
  vertical L8
  horizontal L9
  vertical L10
  coincident L6 P9
  coincident L6 P7
  coincident L5 P8
  equal C3 C4
  equal C1 C4
  equal C1 C2
  coincident P8 P11
  coincident P7 P12
  coincident P10 P13
  coincident P9 P14
  concentric C2 C5
  concentric C1 C6
  concentric C4 C7
  concentric C3 C8
  equal C5 C8
  equal C5 C6
  equal C6 C7
  coincident P1 P19
  concentric C9 C10
  coincident P1 P21
  concentric C9 C12
  dimension "d1" distance P7 P8 = 31
  dimension "d2" distance P2 P3 = 37
  dimension "d3" diameter C1 = 3.4
  dimension "d4" distance L4 P11 = 3
  dimension "d5" diameter C6 = 9
  dimension "d6" diameter C9 = 30
  dimension "d7" diameter C10 = 5
  dimension "d8" diameter C11 = 8
  dimension "d9" distance C11 C12 = 2.5
extrude "Extrude1" new body sketch "Sketch1" profile of L1 L2 L3 L4 C1 C2 C3 C4 C5 C6 C7 C8 along normal blind 7 bodies "circuit_mount_stepper_simple"
extrude "Extrude4" add sketch "Sketch1" profile of L1 L2 L3 L4 C5 C6 C7 C8 C9 to an object offset -3
chamfer "Chamfer4" distance 0.5
fillet "Fillet1" radius 3
fillet "Fillet2" radius 2
chamfer "Chamfer5" distance 0.5
component_insert "Component Insert"
joint "Assemble1" alignAngle 0 alignOffsetX 0 alignOffsetY 0 alignOffsetZ 0
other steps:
joint_origin "JointOrigin1"
named bodies: "circuit_mount_stepper_simple"

design "HW_M5x20-SHCS"
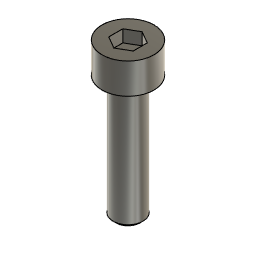
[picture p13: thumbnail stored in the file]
sketch "Sketch1" plane through (0, 0, 0) normal (0, 1, 0) x axis (1, 0, 0)
  line L1 (0, 20) -> (0, -5)
  line L2 (1.95, 20) -> (0, 20)
  line L3 (2.45, 19.5) -> (1.95, 20)
  line L4 (2.45, 0) -> (2.45, 19.5)
  line L5 (4.25, 0) -> (2.45, 0)
  line L6 (4.25, -5) -> (4.25, 0)
  line L7 (0, -5) -> (4.25, -5)
  point P1 (0, 0)
  point P4 (1.95, 20)
  point P5 (2.45, 19.5)
  point P3 (0, 20)
  point P7 (4.25, 0)
  point P8 (4.25, -5)
  point P2 (0, -5)
  vertical L1
  perpendicular L1 L2
  perpendicular L2 L4
  perpendicular L4 L5
  perpendicular L5 L6
  horizontal L7
  coincident P1 L1
  coincident P1 L5
  dimension "d1" distance P1 L2 = 20
  dimension "d2" angle L2 L3 = 45
  dimension "d3" distance P4 P5 = 0.5
  dimension "d4" distance P3 L4 = 2.45 (= "( 4.9 / 2 ) * 1 mm")
  dimension "d5" distance P7 P8 = 5
  dimension "d6" distance P2 P8 = 4.25 (= "( 8.5 / 2 ) * 1 mm")
revolve "Revolve1" sketch "Sketch1" AlongAngle 360
sketch "Sketch2" plane through (0, 0, 5) normal (0, 0, 1) x axis (-1, 0, 0)
  line L1 (0, -2.3094) -> (-2, -1.1547)
  line L2 (2, -1.1547) -> (0, -2.3094)
  line L3 (2, 1.1547) -> (2, -1.1547)
  line L4 (0, 2.3094) -> (2, 1.1547)
  line L5 (-2, 1.1547) -> (0, 2.3094)
  line L6 (-2, -1.1547) -> (-2, 1.1547)
  circle C1 centre (0, 0) radius 4.25
  point P1 (0, 0)
  point P9 (0, 0)
  point P5 (2, -1.1547)
  coincident P1 P9
  vertical L6
  dimension "d8" distance P5 L6 = 4
extrude "Extrude1" cut sketch "Sketch2" profile of L1 L2 L3 L4 L5 L6 against normal blind 2

design "limit_mount" references "HW_M3x16-SHCS", "PP_SWTC_Omron-V154", "HW_M5x8-SHCS"
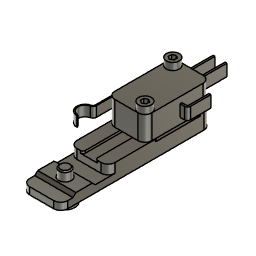
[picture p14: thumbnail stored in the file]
sketch "Sketch1" plane through (0, 0, 0) normal (0, 0, 1) x axis (1, 0, 0)
  line L1 (8.15, -10) -> (-8.15, -10)
  line L2 (8.15, 54.2) -> (8.15, -10)
  line L3 (-8.15, 54.2) -> (8.15, 54.2)
  line L4 (-8.15, -10) -> (-8.15, 54.2)
  line L5 (0, -10) -> (0, 0)
  line L6 (8.15, 10.25) -> (-8.15, 10.25)
  line L7 (-5.15, 29) -> (5.15, 29)
  line L8 (-5.15, 51.2) -> (-5.15, 29)
  line L9 (5.15, 51.2) -> (-5.15, 51.2)
  line L10 (5.15, 29) -> (5.15, 51.2)
  line L11 (0, 0) -> (0, 29)
  line L12 (-2.65, 48.7) -> (-2.65, 54.2)
  line L13 (-8.15, 48.7) -> (-2.65, 48.7)
  line L14 (2.65, 31.5) -> (8.15, 31.5)
  line L15 (2.65, 10.25) -> (2.65, 31.5)
  line L16 (-2.65, 31.5) -> (-8.15, 31.5)
  line L17 (-2.65, 10.25) -> (-2.65, 31.5)
  line L18 (2.65, 48.7) -> (2.65, 54.2)
  line L19 (8.15, 48.7) -> (2.65, 48.7)
  line L20 (-8.15, 26) -> (8.15, 26)
  circle C1 centre (0, 0) radius 2.75
  circle C2 centre (-5.15, 51.2) radius 1.35
  circle C3 centre (5.15, 29) radius 1.35
  circle C4 centre (5.15, 29) radius 2.5
  circle C5 centre (-5.15, 51.2) radius 2.5
  circle C6 centre (-5.15, 29) radius 1.35
  circle C7 centre (5.15, 51.2) radius 1.35
  point P1 (0, 0)
  point P2 (0, 0)
  point P7 (0, 0)
  point P8 (0, -10)
  point P9 (-8.15, 10.25)
  point P10 (8.15, 10.25)
  point P13 (-5.15, 51.2)
  point P15 (-5.15, 51.2)
  point P11 (5.15, 29)
  point P16 (5.15, 29)
  point P17 (0, 29)
  point P18 (0, 0)
  point P19 (-2.65, 54.2)
  point P21 (-8.15, 48.7)
  point P22 (8.15, 31.5)
  point P24 (2.65, 10.25)
  point P31 (2.65, 54.2)
  point P20 (-2.65, 48.7)
  point P32 (2.65, 48.7)
  point P33 (8.15, 48.7)
  point P27 (-8.15, 31.5)
  point P23 (2.65, 31.5)
  point P28 (-2.65, 31.5)
  point P29 (-2.65, 10.25)
  point P35 (8.15, 26)
  point P36 (-8.15, 26)
  point P3 (-8.15, -10)
  point P4 (8.15, -10)
  point P14 (5.15, 51.2)
  point P25 (5.15, 29)
  point P26 (-5.15, 51.2)
  coincident P1 P2
  horizontal L1
  vertical L2
  horizontal L3
  vertical L4
  coincident P1 P7
  midpoint L1 P8
  vertical L5
  coincident L4 P9
  coincident L2 P10
  perpendicular L2 L6
  horizontal L7
  vertical L8
  horizontal L9
  vertical L10
  coincident P13 P15
  coincident P11 P16
  equal C2 C3
  midpoint L7 P17
  coincident P1 P18
  vertical L11
  coincident L3 P19
  perpendicular L3 L12
  coincident L4 P21
  perpendicular L4 L13
  coincident L2 P22
  perpendicular L10 L14
  coincident L6 P24
  perpendicular L6 L15
  concentric C3 C4
  concentric C2 C5
  equal C4 C5
  tangent L12 C5
  tangent L13 C5
  tangent L14 C4
  tangent L15 C4
  symmetric C2 L11 C7
  symmetric C3 L11 C6
  symmetric L11 P19 P31
  symmetric L11 P20 P32
  symmetric L11 P21 P33
  symmetric L11 P22 P27
  symmetric L11 P23 P28
  symmetric L11 P24 P29
  coincident L2 P35
  coincident L4 P36
  perpendicular L4 L20
  dimension "d1" diameter C1 = 5.5
  dimension "d2" distance P3 P4 = 16.3
  dimension "d3" distance P7 P8 = 10
  dimension "d4" distance P1 L6 = 10.25
  dimension "d5" diameter C2 = 2.7
  dimension "d6" distance P13 P14 = 10.3
  dimension "d7" distance P11 P14 = 22.2
  dimension "d8" distance L2 L10 = 3
  dimension "d9" distance P2 P25 = 29
  dimension "d10" diameter C4 = 5
  dimension "d11" distance L3 P26 = 3
  dimension "d40" distance P25 L20 = 3
extrude "Extrude1" new body sketch "Sketch1" profile of C1 L1 L2 L3 L4 L6 C2 C3 L12 L13 L14 L15 L16 L17 C6 L18 L19 C7 against normal blind 3 bodies "limit_mount"
extrude "Extrude2" add sketch "Sketch1" profile of L2 L3 L4 L6 C2 C3 L12 L13 L14 L15 L16 L17 C6 L18 L19 C7 along normal blind 4
extrude "Extrude3" add sketch "Sketch1" profile of L2 L3 L4 L6 L12 L13 L14 L15 L16 L17 C6 L18 L19 C7 to an object offset -1
fillet "Fillet1" radius 3
fillet "Fillet2" radius 1
chamfer "Chamfer2" distance 0.5
component_insert "Component Insert1"
joint "Assemble1" alignAngle -270 alignOffsetX 0 alignOffsetY 0 alignOffsetZ 0
sketch "Sketch2" plane through (0, 0, 0) normal (1, 0, 0) x axis (0, 1, 0)
  line L1 (-4.75, 0) -> (4.75, 0)
  line L2 (-2.75, 2) -> (-4.75, 0)
  line L3 (2.75, 2) -> (-2.75, 2)
  line L4 (4.75, 0) -> (2.75, 2)
  line L5 (0, 2) -> (0, 0)
  line L6 (-3.5, 1.25) -> (3.5, 1.25)
  point P1 (0, 0)
  point P6 (0, 0)
  point P7 (0, 2)
  point P8 (3.5, 1.25)
  point P9 (-3.5, 1.25)
  point P4 (-2.75, 2)
  point P5 (2.75, 2)
  horizontal L1
  parallel L1 L3
  coincident P1 P6
  midpoint L3 P7
  vertical L5
  coincident P1 L1
  coincident L4 P8
  coincident L2 P9
  horizontal L6
  perpendicular L2 L4
  dimension "d30" angle L3 L4 = 45
  dimension "d31" distance P4 P5 = 5.5
  dimension "d32" distance P1 L6 = 1.25
  dimension "d33" distance P6 P7 = 2
extrude "Extrude4" add sketch "Sketch2" profile of L1 L2 L4 L6 to an object Side2Offset 0
extrude "Extrude5" cut of existing geometry blind -1.25
component_insert "Component Insert2"
component_insert "Component Insert3"
component_insert "Component Insert4"
joint "Assemble2" alignAngle 0 alignOffsetX 0 alignOffsetY 0 alignOffsetZ 0
joint "Assemble3" alignAngle 90 alignOffsetX 0 alignOffsetY 0 alignOffsetZ 0
joint "Assemble4" alignAngle 90 alignOffsetX 0 alignOffsetY 0 alignOffsetZ 0
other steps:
joint_origin "JointOrigin2"
joint_origin "JointOrigin3"
named bodies: "limit_mount"

design "belt_motor_mount" references "PP_ACTU_N17-Stepper", "PP_TRNS_GT2-Pulley-20T-6mm", "HW_M5x8-SHCS", "HW_M3x8-SHCS"
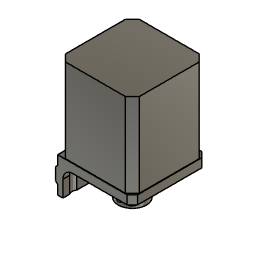
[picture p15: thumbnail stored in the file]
sketch "Sketch1" plane through (0, 0, 0) normal (0, 0, 1) x axis (1, 0, 0)
  line L1 (0.2162, 21.15) -> (42.5162, 21.15)
  line L2 (0.2162, -21.15) -> (0.2162, 21.15)
  line L3 (42.5162, -21.15) -> (0.2162, -21.15)
  line L4 (42.5162, 21.15) -> (42.5162, -21.15)
  line L5 (0.2162, -21.15) -> (42.5162, 21.15)
  line L6 (42.5162, -21.15) -> (0.2162, 21.15)
  line L7 (0, 0) -> (21.3662, 0)
  line L8 (36.8662, 15.5) -> (5.8662, 15.5)
  line L9 (36.8662, -15.5) -> (36.8662, 15.5)
  line L10 (5.8662, -15.5) -> (36.8662, -15.5)
  line L11 (5.8662, 15.5) -> (5.8662, -15.5)
  line L12 (3, -13.4913) -> (3, 13.4913)
  line L13 (0, 21.4) -> (0, -21.4)
  line L14 (42.7662, 21.4) -> (0, 21.4)
  line L15 (42.7662, -21.4) -> (42.7662, 21.4)
  line L16 (0, -21.4) -> (42.7662, -21.4)
  line L17 (3, 21.4) -> (3, 17.5087)
  line L18 (3, 3.5) -> (10.8851, 3.5)
  line L19 (3, -3.5) -> (10.8851, -3.5)
  line L20 (3, -21.4) -> (3, -17.5087)
  circle C1 centre (21.3662, 0) radius 6.3662
  circle C2 centre (36.8662, 15.5) radius 1.75
  circle C3 centre (36.8662, -15.5) radius 1.75
  circle C4 centre (5.8662, -15.5) radius 1.75
  circle C5 centre (5.8662, 15.5) radius 1.75
  circle C6 centre (21.3662, 0) radius 11.05
  circle C7 centre (5.8662, -15.5) radius 3.5
  circle C8 centre (5.8662, 15.5) radius 3.5
  point P6 (21.3662, 0)
  point P7 (21.3662, 0)
  point P8 (21.3662, 0)
  point P1 (0, 0)
  point P9 (0, 0)
  point P10 (15, 0)
  point P13 (36.8662, -15.5)
  point P11 (5.8662, 15.5)
  point P12 (36.8662, 15.5)
  point P19 (21.3662, 0)
  point P15 (36.8662, 15.5)
  point P16 (36.8662, -15.5)
  point P14 (5.8662, -15.5)
  point P17 (5.8662, -15.5)
  point P18 (5.8662, 15.5)
  point P20 (3, 13.4913)
  point P21 (3, -13.4913)
  point P24 (0, -21.4)
  point P28 (0, -21.4)
  point P29 (3, 17.5087)
  point P30 (3, 21.4)
  point P31 (10.8851, 3.5)
  point P32 (3, 3.5)
  point P33 (10.8851, -3.5)
  point P34 (3, -3.5)
  point P35 (3, -17.5087)
  point P36 (3, -21.4)
  point P2 (42.5162, 21.15)
  point P5 (42.5162, -21.15)
  point P3 (0.2162, 21.15)
  point P26 (42.7662, 21.4)
  horizontal L1
  perpendicular L1 L2
  parallel L1 L3
  parallel L2 L4
  coincident L5 P6
  coincident L6 P6
  equal L1 L2
  coincident P6 P7
  coincident P6 P8
  coincident P1 P9
  horizontal L7
  coincident C1 P10
  coincident L7 P10
  horizontal L8
  vertical L9
  horizontal L10
  vertical L11
  coincident L6 P13
  coincident L6 P11
  coincident L5 P12
  equal C4 C5
  equal C3 C5
  equal C2 C3
  coincident P6 P19
  coincident P12 P15
  coincident P13 P16
  coincident P14 P17
  coincident P11 P18
  vertical L12
  concentric C4 C7
  concentric C5 C8
  equal C7 C8
  coincident P20 C8
  coincident P21 C7
  perpendicular L1 L13
  midpoint P1 L13
  perpendicular L13 L14
  perpendicular L14 L15
  perpendicular L15 L16
  coincident P24 P28
  coincident C8 P29
  coincident L14 P30
  perpendicular L14 L17
  coincident P20 L17
  coincident C6 P31
  coincident L12 P32
  perpendicular L12 L18
  coincident C6 P33
  coincident L12 P34
  perpendicular L12 L19
  coincident C7 P35
  coincident L16 P36
  perpendicular L16 L20
  coincident P21 L20
  dimension "d1" diameter C1 = 12.7324 (= "( 20 * 2 / PI ) * 1 mm")
  dimension "d2" distance P1 P10 = 15
  dimension "d3" distance P2 P5 = 42.3
  dimension "d4" diameter C2 = 3.5
  dimension "d5" diameter C6 = 22.1
  dimension "d6" distance P12 P13 = 31
  dimension "d7" distance P1 L12 = 3
  dimension "d8" diameter C8 = 7
  dimension "d9" distance P3 L14 = 0.25
  dimension "d10" distance L4 P26 = 0.25
  dimension "d38" distance P1 L18 = 3.5
  dimension "d39" distance P1 L19 = 3.5 (= "d38")
extrude "Extrude1" new body sketch "Sketch1" profile of C2 C3 C4 C5 C6 L12 C7 C8 L13 L14 L15 L16 along normal blind 5
extrude "Extrude2" add sketch "Sketch1" profile of C6 L12 C7 C8 L13 L14 L16 L17 L18 L19 L20 against normal blind 15
sketch "Sketch2" plane through (0, 0, 0) normal (-1, 0, 0) x axis (0, -1, 0)
  line L1 (21.4, 5) -> (21.4, -15)
  line L2 (-21.4, 5) -> (21.4, 5)
  line L3 (-21.4, -15) -> (-21.4, 5)
  line L4 (21.4, -15) -> (-21.4, -15)
  line L5 (-21.4, -5) -> (21.4, -5)
  circle C1 centre (-8.4, -5) radius 2.75
  circle C2 centre (-8.4, -5) radius 4
  circle C3 centre (8.4, -5) radius 2.75
  circle C4 centre (8.4, -5) radius 4
  point P6 (21.4, -5)
  point P7 (-21.4, -5)
  point P8 (-8.4, -5)
  point P10 (8.4, -5)
  point P4 (-21.4, 5)
  point P9 (-8.4, -5)
  point P3 (21.4, 5)
  point P11 (8.4, -5)
  midpoint L1 P6
  midpoint L3 P7
  coincident L5 P8
  concentric C1 C2
  coincident L5 P10
  concentric C3 C4
  equal C2 C4
  equal C1 C3
  dimension "d17" distance P4 P9 = 13
  dimension "d18" distance P3 P11 = 13 (= "d17")
  dimension "d19" diameter C1 = 5.5
  dimension "d20" diameter C2 = 8
extrude "Extrude3" cut sketch "Sketch2" profile of C1 C3 no distance stored
chamfer "Chamfer2" distance 3
fillet "Fillet4" ChordLen 7.5
fillet "Fillet5" ChordLen 1
sketch "Sketch4" plane through (0, 21.4, 0) normal (0, 1, 0) x axis (-1, 0, 0)
  line L1 (-39.7662, 0) -> (-39.7662, 5)
  line L2 (-3, 0) -> (-39.7662, 0)
  line L3 (-3, -15) -> (-3, 0)
  line L4 (0, -15) -> (-3, -15)
  line L5 (0, 5) -> (0, -15)
  line L6 (-39.7662, 5) -> (0, 5)
  line L7 (2, -2.25) -> (0, -0.25)
  line L8 (2, -7.75) -> (2, -2.25)
  line L9 (0, -9.75) -> (2, -7.75)
  line L10 (0, -9.75) -> (0, -0.25)
  line L11 (1.25, -8.5) -> (1.25, -1.5)
  point P9 (0, -0.25)
  point P12 (0, -9.75)
  point P8 (0, -5)
  point P13 (1.25, -1.5)
  point P14 (1.25, -8.5)
  point P10 (2, -2.25)
  point P11 (2, -7.75)
  coincident L5 P9
  parallel L5 L8
  coincident L5 P12
  perpendicular L7 L9
  midpoint P8 L10
  coincident L7 P13
  coincident L9 P14
  parallel L8 L11
  dimension "d68" distance P8 L8 = 2
  dimension "d69" angle L7 L8 = 45
  dimension "d70" distance P10 P11 = 5.5
  dimension "d71" distance L10 L11 = 1.25
extrude "Extrude4" add sketch "Sketch4" profile of L5 L7 L9 L10 L11 to an object
extrude "Extrude5" cut of existing geometry no distance stored
component_insert "Component Insert1"
joint "Assemble1" alignAngle 0 alignOffsetX 0 alignOffsetY 0 alignOffsetZ 0
component_insert "Component Insert2"
joint "Assemble2" alignAngle 0 alignOffsetX 0 alignOffsetY 0 alignOffsetZ -3
component_insert "Component Insert4"
joint "Assemble3" alignAngle 0 alignOffsetX 0 alignOffsetY 0 alignOffsetZ 0
component_insert "Component Insert5"
joint "Assemble4" alignAngle 0 alignOffsetX 0 alignOffsetY 0 alignOffsetZ 0
component_insert "Component Insert6"
joint "Assemble5" alignAngle 0 alignOffsetX 0 alignOffsetY 0 alignOffsetZ 0
component_insert "Component Insert7"
component_insert "Component Insert8"
component_insert "Component Insert9"
joint "Assemble6" alignAngle 0 alignOffsetX 0 alignOffsetY 0 alignOffsetZ 0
